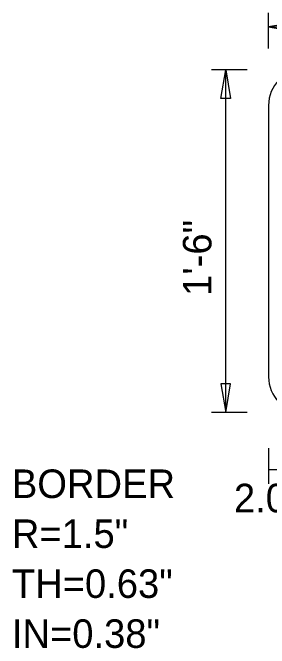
# Model space of a CAD drawing. Extents: x 1788.1 to 1851.2, y 237.2 to 283.4.
# Drawn here: x 1804.568 to 1805.917, y 249.428 to 252.768 of the extents above; entities that cross this region are included whole.
import ezdxf

# ---------------------------------------------------------------- set-up
doc = ezdxf.new("R2010")
doc.units = 0
for name, color, linetype in [('GSBWFILL', 7, 'Continuous'), ('GSCOLORFILL', 7, 'Continuous'), ('GSDIMS', 7, 'Continuous'), ('GSOUTLINE', 7, 'Continuous')]:
    doc.layers.add(name, color=color, linetype=linetype)

msp = doc.modelspace()

# ---------------------------------------------------------------- linework, layer by layer
at = {"layer": 'GSBWFILL'}
msp.add_line((1805.9125, 252.2802), (1805.9125, 250.8552), dxfattribs=at)
msp.add_line((1805.9125, 252.2802), (1805.9125, 250.8552), dxfattribs=at)
for centre, start, end in [((1806.1, 252.2802), 90, 180), ((1806.1, 252.2802), 90, 180), ((1806.1, 250.8552), 180, 270), ((1806.1, 250.8552), 180, 270)]:
    msp.add_arc(centre, 0.1875, start, end, dxfattribs=at)
at = {"layer": 'GSCOLORFILL'}
msp.add_line((1805.9125, 252.2802), (1805.9125, 250.8552), dxfattribs=at)
msp.add_line((1805.9125, 252.2802), (1805.9125, 250.8552), dxfattribs=at)
msp.add_line((1805.9125, 252.2802), (1805.9125, 250.8552), dxfattribs=at)
msp.add_line((1805.9125, 252.2802), (1805.9125, 250.8552), dxfattribs=at)
for centre, start, end in [((1806.1, 252.2802), 90, 180), ((1806.1, 252.2802), 90, 180), ((1806.1, 252.2802), 90, 180), ((1806.1, 252.2802), 90, 180), ((1806.1, 250.8552), 180, 270), ((1806.1, 250.8552), 180, 270), ((1806.1, 250.8552), 180, 270), ((1806.1, 250.8552), 180, 270)]:
    msp.add_arc(centre, 0.1875, start, end, dxfattribs=at)
at = {"layer": 'GSDIMS'}
for p, q in [((1805.9125, 252.5802), (1805.9125, 252.7677)), ((1805.9125, 252.6927), (1810.7125, 252.6927)), ((1805.9125, 252.5802), (1805.9125, 252.5802)), ((1805.8, 252.4677), (1805.6125, 252.4677)), ((1805.6875, 250.6677), (1805.6875, 252.4677)), ((1805.8, 252.4677), (1805.8, 252.4677)), ((1805.8, 250.6677), (1805.6125, 250.6677)), ((1805.8, 250.6677), (1805.8, 250.6677)), ((1805.9125, 250.4802), (1805.9125, 250.2927)), ((1805.9125, 250.4802), (1805.9125, 250.2927)), ((1805.9125, 250.3677), (1806.1175, 250.3677))]:
    msp.add_line(p, q, dxfattribs=at)
for points in [[(1805.9125, 252.6927), (1806.0625, 252.6677), (1806.0625, 252.7177)], [(1805.6875, 252.4677), (1805.7125, 252.3177), (1805.6625, 252.3177)], [(1805.6875, 250.6677), (1805.7125, 250.8177), (1805.6625, 250.8177)]]:
    msp.add_lwpolyline(points, close=True, dxfattribs=at)
at = {"layer": 'GSOUTLINE'}
msp.add_line((1805.9125, 252.2802), (1805.9125, 250.8552), dxfattribs=at)
msp.add_line((1805.9125, 252.2802), (1805.9125, 250.8552), dxfattribs=at)
for centre, start, end in [((1806.1, 252.2802), 90, 180), ((1806.1, 252.2802), 90, 180), ((1806.1, 250.8552), 180, 270), ((1806.1, 250.8552), 180, 270)]:
    msp.add_arc(centre, 0.1875, start, end, dxfattribs=at)

# ---------------------------------------------------------------- texts
at = {"layer": 'GSDIMS'}
msp.add_text('1\'-6"', height=0.15, rotation=90, dxfattribs=at).set_placement((1805.6125, 251.2799))
for s, p in [('BORDER', (1804.563, 250.2177)), ('2.05"', (1805.7307, 250.1427)), ('R=1.5"', (1804.563, 249.9552)), ('TH=0.63"', (1804.563, 249.6927)), ('IN=0.38"', (1804.563, 249.4302))]:
    msp.add_text(s, height=0.15, dxfattribs=at).set_placement(p)

doc.saveas('drawing.dxf')
